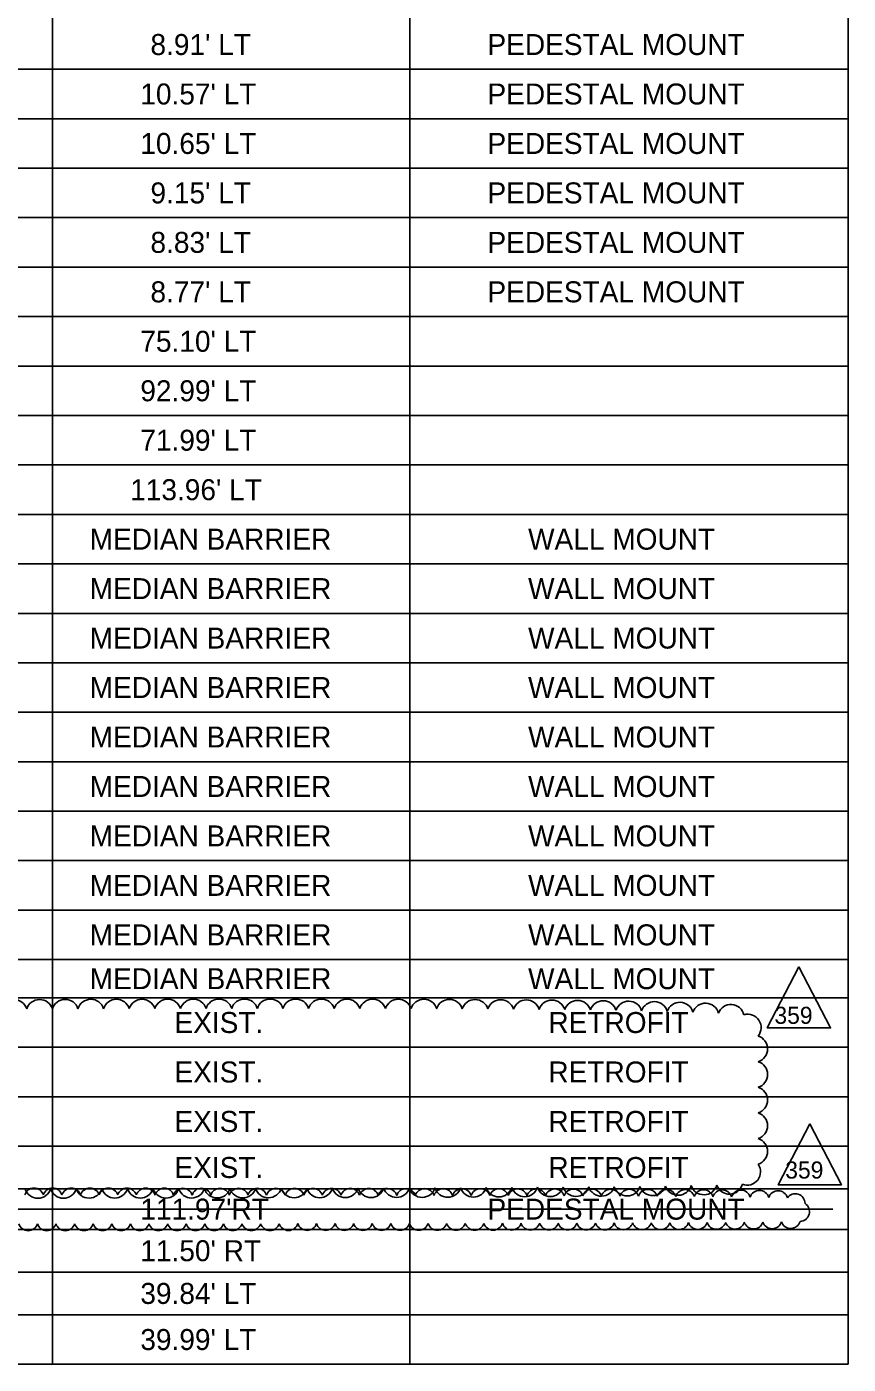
# Model space of a CAD drawing. Extents: x -818.1 to -802.4, y -2221.2 to -2187.7.
# Drawn here: x -812.426 to -809.686, y -2206.269 to -2201.807 of the extents above; entities that cross this region are included whole.
import ezdxf

# ---------------------------------------------------------------- set-up
doc = ezdxf.new("R2010")
doc.units = 0
for name, color, linetype in [('PlotBorder_dp', 7, 'Continuous'), ('SheetBorder_dp', 7, 'Continuous'), ('SheetLines_dp', 7, 'Continuous'), ('TextMinor', 7, 'Continuous'), ('TextTitle', 7, 'Continuous')]:
    doc.layers.add(name, color=color, linetype=linetype)

msp = doc.modelspace()

# ---------------------------------------------------------------- linework, layer by layer
at = {"layer": 'PlotBorder_dp'}
for p, q in [((-812.3407, -2199.8042), (-812.3407, -2206.2692)), ((-812.3407, -2199.8042), (-812.3407, -2206.2692)), ((-811.1482, -2199.8042), (-811.1482, -2206.2692)), ((-811.1482, -2199.8042), (-811.1482, -2206.2692))]:
    msp.add_line(p, q, dxfattribs=at)
at = {"layer": 'SheetLines_dp'}
for p, q in [((-809.6857, -2199.4742), (-809.6857, -2206.2692)), ((-817.2082, -2206.2692), (-811.1482, -2206.2692)), ((-811.1482, -2206.2692), (-809.6857, -2206.2692))]:
    msp.add_line(p, q, dxfattribs=at)
at = {"layer": 'TextMinor'}
for p, q in [((-817.2082, -2201.9492), (-809.6857, -2201.9492)), ((-817.2082, -2201.9492), (-809.6857, -2201.9492)), ((-817.2082, -2202.1142), (-809.6857, -2202.1142)), ((-817.2082, -2202.1142), (-809.6857, -2202.1142)), ((-817.2082, -2202.2792), (-809.6857, -2202.2792)), ((-817.2082, -2202.2792), (-809.6857, -2202.2792)), ((-817.2082, -2202.4442), (-809.6857, -2202.4442)), ((-817.2082, -2202.4442), (-809.6857, -2202.4442)), ((-817.2082, -2202.6092), (-809.6857, -2202.6092)), ((-817.2082, -2202.6092), (-809.6857, -2202.6092)), ((-817.2082, -2202.7742), (-809.6857, -2202.7742)), ((-817.2082, -2202.7742), (-809.6857, -2202.7742)), ((-817.2082, -2202.9392), (-809.6857, -2202.9392)), ((-817.2082, -2202.9392), (-809.6857, -2202.9392)), ((-817.2082, -2203.1042), (-809.6857, -2203.1042)), ((-817.2082, -2203.1042), (-809.6857, -2203.1042)), ((-817.2082, -2203.2692), (-809.6857, -2203.2692)), ((-817.2082, -2203.2692), (-809.6857, -2203.2692)), ((-817.2082, -2203.4342), (-809.6857, -2203.4342)), ((-817.2082, -2203.4342), (-809.6857, -2203.4342)), ((-817.2082, -2203.5992), (-809.6857, -2203.5992)), ((-817.2082, -2203.5992), (-809.6857, -2203.5992)), ((-817.2082, -2203.7642), (-809.6857, -2203.7642)), ((-817.2082, -2203.7642), (-809.6857, -2203.7642)), ((-817.2082, -2203.9292), (-809.6857, -2203.9292)), ((-817.2082, -2203.9292), (-809.6857, -2203.9292)), ((-817.2082, -2204.0942), (-809.6857, -2204.0942)), ((-817.2082, -2204.0942), (-809.6857, -2204.0942)), ((-817.2082, -2204.2592), (-809.6857, -2204.2592)), ((-817.2082, -2204.2592), (-809.6857, -2204.2592)), ((-817.2082, -2204.4242), (-809.6857, -2204.4242)), ((-817.2082, -2204.4242), (-809.6857, -2204.4242)), ((-817.2082, -2204.5892), (-809.6857, -2204.5892)), ((-817.2082, -2204.5892), (-809.6857, -2204.5892)), ((-817.2082, -2204.7542), (-809.6857, -2204.7542)), ((-817.2082, -2204.7542), (-809.6857, -2204.7542)), ((-817.2082, -2204.9192), (-809.6857, -2204.9192)), ((-816.2257, -2204.9192), (-809.6857, -2204.9192)), ((-817.2082, -2205.0467), (-809.6857, -2205.0467)), ((-817.2082, -2205.0467), (-809.6857, -2205.0467)), ((-817.2082, -2205.2117), (-809.6857, -2205.2117)), ((-814.2457, -2205.2117), (-809.6857, -2205.2117)), ((-817.2082, -2205.3767), (-809.6857, -2205.3767)), ((-812.9482, -2205.3767), (-809.6857, -2205.3767)), ((-817.2082, -2205.5417), (-809.6857, -2205.5417)), ((-814.2457, -2205.5417), (-809.6857, -2205.5417)), ((-817.2082, -2205.6842), (-809.6857, -2205.6842)), ((-812.9482, -2205.6842), (-809.6857, -2205.6842)), ((-817.2082, -2205.8192), (-809.6857, -2205.8192)), ((-816.7882, -2205.8192), (-811.1482, -2205.8192)), ((-817.2082, -2205.9617), (-809.6857, -2205.9617)), ((-817.2082, -2206.1042), (-809.6857, -2206.1042)), ((-813.6457, -2206.1042), (-811.1482, -2206.1042))]:
    msp.add_line(p, q, dxfattribs=at)
at = {"layer": 'TextTitle'}
msp.add_line((-817.0974, -2205.7517), (-809.7376, -2205.7517), dxfattribs=at)
for points in [[(-809.85, -2204.9439), (-809.9557, -2205.1473), (-809.7444, -2205.1473)], [(-809.8139, -2205.4676), (-809.9195, -2205.6711), (-809.7083, -2205.6711)]]:
    msp.add_lwpolyline(points, close=True, dxfattribs=at)
for centre, radius, start, end in [((-812.2982, -2205.0969), 0.0448, 17.6898, 162.6898), ((-812.2127, -2205.0966), 0.0448, 17.6723, 162.6723), ((-812.1272, -2205.0964), 0.0448, 17.6538, 162.6538), ((-812.0418, -2205.0962), 0.0448, 17.6341, 162.6341), ((-811.9563, -2205.096), 0.0448, 17.6131, 162.6131), ((-811.8708, -2205.0959), 0.0448, 17.5908, 162.5908), ((-811.7854, -2205.0957), 0.0448, 17.5668, 162.5668), ((-811.6999, -2205.0957), 0.0448, 17.5411, 162.5411), ((-811.6144, -2205.0956), 0.0448, 17.5134, 162.5134), ((-811.529, -2205.0956), 0.0448, 17.4834, 162.4834), ((-811.4435, -2205.0957), 0.0448, 17.4509, 162.4509), ((-811.358, -2205.0958), 0.0448, 17.4153, 162.4153), ((-811.2726, -2205.0959), 0.0448, 17.3762, 162.3762), ((-811.1871, -2205.0961), 0.0448, 17.333, 162.333), ((-811.1016, -2205.0964), 0.0448, 17.285, 162.285), ((-811.0162, -2205.0968), 0.0448, 17.231, 162.231), ((-812.4691, -2205.0975), 0.0448, 17.7221, 162.7221), ((-812.3837, -2205.0972), 0.0448, 17.7064, 162.7064), ((-810.9307, -2205.0972), 0.0448, 17.1699, 162.1699), ((-810.8452, -2205.0978), 0.0448, 17.0999, 162.0999), ((-810.7598, -2205.0984), 0.0448, 17.0185, 162.0185), ((-810.6743, -2205.0992), 0.0448, 16.9224, 161.9224), ((-810.5889, -2205.1002), 0.0448, 16.8064, 161.8064), ((-810.5035, -2205.1013), 0.0448, 16.6627, 161.6627), ((-810.418, -2205.1027), 0.0448, 16.4778, 161.4778), ((-810.3326, -2205.1044), 0.0448, 16.2276, 161.2276), ((-810.2473, -2205.1066), 0.0448, 15.861, 160.861), ((-810.162, -2205.1095), 0.0448, 15.2441, 160.2441), ((-810.077, -2205.1139), 0.0448, 13.804, 158.804), ((-810.021, -2205.1462), 0.0448, 321.1304, 106.1304), ((-809.9996, -2205.2171), 0.0448, 287.5, 72.5), ((-809.9996, -2205.3025), 0.0448, 287.5, 72.5), ((-809.9996, -2205.388), 0.0448, 287.5, 72.5), ((-809.9996, -2205.4735), 0.0448, 287.5, 72.5), ((-809.9996, -2205.559), 0.0448, 287.5, 72.5), ((-810.0231, -2205.627), 0.0448, 249.3736, 34.3736), ((-810.5091, -2205.6637), 0.0448, 198.0389, 343.0389), ((-810.4236, -2205.6629), 0.0448, 198.1252, 343.1252), ((-810.3382, -2205.6618), 0.0448, 198.2415, 343.2415), ((-810.2527, -2205.6606), 0.0448, 198.4108, 343.4108), ((-810.1673, -2205.659), 0.0448, 198.6925, 343.6925), ((-810.082, -2205.6568), 0.0448, 199.3286, 344.3286), ((-812.4021, -2205.714), 0.0325, 17.463, 162.463), ((-812.3894, -2205.6704), 0.0448, 197.5477, 342.5477), ((-812.3401, -2205.714), 0.0325, 17.4602, 162.4602), ((-812.3039, -2205.6704), 0.0448, 197.5556, 342.5556), ((-812.278, -2205.7141), 0.0325, 17.4573, 162.4573), ((-812.2184, -2205.6703), 0.0448, 197.5639, 342.5639), ((-812.216, -2205.7141), 0.0325, 17.4543, 162.4543), ((-812.1539, -2205.7142), 0.0325, 17.4512, 162.4512), ((-812.133, -2205.6702), 0.0448, 197.5726, 342.5726), ((-812.0919, -2205.7142), 0.0325, 17.448, 162.448), ((-812.0475, -2205.67), 0.0448, 197.5819, 342.5819), ((-812.0298, -2205.7143), 0.0325, 17.4446, 162.4446), ((-811.962, -2205.6699), 0.0448, 197.5918, 342.5918), ((-811.9677, -2205.7143), 0.0325, 17.4411, 162.4411), ((-811.9057, -2205.7144), 0.0325, 17.4374, 162.4374), ((-811.8765, -2205.6698), 0.0448, 197.6024, 342.6024), ((-811.8436, -2205.7145), 0.0325, 17.4335, 162.4335), ((-811.7911, -2205.6696), 0.0448, 197.6137, 342.6137), ((-811.7816, -2205.7146), 0.0325, 17.4294, 162.4294), ((-811.7195, -2205.7146), 0.0325, 17.4252, 162.4252), ((-811.7056, -2205.6694), 0.0448, 197.6259, 342.6259), ((-811.6575, -2205.7147), 0.0325, 17.4207, 162.4207), ((-811.6201, -2205.6692), 0.0448, 197.639, 342.639), ((-811.5954, -2205.7148), 0.0325, 17.416, 162.416), ((-811.5347, -2205.669), 0.0448, 197.6531, 342.6531), ((-811.5333, -2205.7149), 0.0325, 17.411, 162.411), ((-811.4713, -2205.715), 0.0325, 17.4057, 162.4057), ((-811.4492, -2205.6688), 0.0448, 197.6685, 342.6685), ((-811.4092, -2205.7151), 0.0325, 17.4002, 162.4002), ((-811.3637, -2205.6685), 0.0448, 197.6853, 342.6853), ((-811.3472, -2205.7152), 0.0325, 17.3942, 162.3942), ((-811.2782, -2205.6682), 0.0448, 197.7038, 342.7038), ((-811.2851, -2205.7153), 0.0325, 17.3879, 162.3879), ((-811.223, -2205.7155), 0.0325, 17.3812, 162.3812), ((-811.1928, -2205.6679), 0.0448, 197.7241, 342.7241), ((-811.161, -2205.7156), 0.0325, 17.374, 162.374), ((-811.1073, -2205.6676), 0.0448, 197.7468, 342.7468), ((-811.0989, -2205.7157), 0.0325, 17.3662, 162.3662), ((-811.0369, -2205.7159), 0.0325, 17.3579, 162.3579), ((-811.0218, -2205.6672), 0.0448, 197.7722, 342.7722), ((-810.9748, -2205.716), 0.0325, 17.3488, 162.3488), ((-810.9364, -2205.6667), 0.0448, 197.801, 342.801), ((-810.9128, -2205.7162), 0.0325, 17.339, 162.339), ((-810.8509, -2205.6663), 0.0448, 197.8339, 342.8339), ((-810.8507, -2205.7164), 0.0325, 17.3282, 162.3282), ((-810.7887, -2205.7166), 0.0325, 17.3164, 162.3164), ((-810.7654, -2205.6657), 0.0448, 197.8722, 342.8722), ((-810.7266, -2205.7168), 0.0325, 17.3033, 162.3033), ((-810.68, -2205.6651), 0.0448, 197.9173, 342.9173), ((-810.6645, -2205.717), 0.0325, 17.2888, 162.2888), ((-810.5945, -2205.6645), 0.0448, 197.9717, 342.9717), ((-810.6025, -2205.7172), 0.0325, 17.2724, 162.2724), ((-810.5404, -2205.7175), 0.0325, 17.2538, 162.2538), ((-810.4784, -2205.7178), 0.0325, 17.2324, 162.2324), ((-810.4163, -2205.7181), 0.0325, 17.2076, 162.2076), ((-810.3543, -2205.7184), 0.0325, 17.1781, 162.1781), ((-810.2922, -2205.7188), 0.0325, 17.1424, 162.1424), ((-810.2302, -2205.7192), 0.0325, 17.098, 162.098), ((-810.1681, -2205.7197), 0.0325, 17.0404, 162.0404), ((-810.1061, -2205.7202), 0.0325, 16.9617, 161.9617), ((-810.044, -2205.7208), 0.0325, 16.8443, 161.8443), ((-809.982, -2205.7217), 0.0325, 16.6401, 161.6401), ((-809.9201, -2205.7229), 0.0325, 16.1079, 161.1079), ((-809.8623, -2205.7327), 0.0325, 359.6037, 144.6037), ((-809.8475, -2205.7602), 0.0325, 271.8825, 56.8825), ((-812.4218, -2205.7911), 0.0325, 197.5287, 342.5287), ((-812.3598, -2205.7911), 0.0325, 197.531, 342.531), ((-812.2977, -2205.7911), 0.0325, 197.5333, 342.5333), ((-812.2356, -2205.791), 0.0325, 197.5357, 342.5357), ((-812.1736, -2205.791), 0.0325, 197.5382, 342.5382), ((-812.1115, -2205.791), 0.0325, 197.5408, 342.5408), ((-812.0495, -2205.7909), 0.0325, 197.5435, 342.5435), ((-811.9874, -2205.7909), 0.0325, 197.5464, 342.5464), ((-811.9254, -2205.7908), 0.0325, 197.5493, 342.5493), ((-811.8633, -2205.7908), 0.0325, 197.5524, 342.5524), ((-811.8012, -2205.7907), 0.0325, 197.5557, 342.5557), ((-811.7392, -2205.7906), 0.0325, 197.5591, 342.5591), ((-811.6771, -2205.7906), 0.0325, 197.5627, 342.5627), ((-811.6151, -2205.7905), 0.0325, 197.5664, 342.5664), ((-811.553, -2205.7904), 0.0325, 197.5704, 342.5704), ((-811.491, -2205.7903), 0.0325, 197.5745, 342.5745), ((-811.4289, -2205.7903), 0.0325, 197.579, 342.579), ((-811.3668, -2205.7902), 0.0325, 197.5836, 342.5836), ((-811.3048, -2205.7901), 0.0325, 197.5886, 342.5886), ((-811.2427, -2205.79), 0.0325, 197.5939, 342.5939), ((-811.1807, -2205.7899), 0.0325, 197.5996, 342.5996), ((-811.1186, -2205.7898), 0.0325, 197.6056, 342.6056), ((-811.0565, -2205.7897), 0.0325, 197.6121, 342.6121), ((-810.9945, -2205.7895), 0.0325, 197.6192, 342.6192), ((-810.9324, -2205.7894), 0.0325, 197.6268, 342.6268), ((-810.8704, -2205.7893), 0.0325, 197.6351, 342.6351), ((-810.8083, -2205.7891), 0.0325, 197.6441, 342.6441), ((-810.7463, -2205.7889), 0.0325, 197.6541, 342.6541), ((-810.6842, -2205.7888), 0.0325, 197.6651, 342.6651), ((-810.6222, -2205.7886), 0.0325, 197.6774, 342.6774), ((-810.5601, -2205.7884), 0.0325, 197.6912, 342.6912), ((-810.498, -2205.7882), 0.0325, 197.7069, 342.7069), ((-810.436, -2205.7879), 0.0325, 197.725, 342.725), ((-810.3739, -2205.7877), 0.0325, 197.7461, 342.7461), ((-810.3119, -2205.7874), 0.0325, 197.7711, 342.7711), ((-810.2498, -2205.7871), 0.0325, 197.8015, 342.8015), ((-810.1878, -2205.7867), 0.0325, 197.8394, 342.8394), ((-810.1257, -2205.7863), 0.0325, 197.8888, 342.8888), ((-810.0637, -2205.7859), 0.0325, 197.9568, 342.9568), ((-810.0016, -2205.7853), 0.0325, 198.0592, 343.0592), ((-809.9396, -2205.7846), 0.0325, 198.2413, 343.2413), ((-809.8777, -2205.7836), 0.0325, 198.7573, 343.7573)]:
    msp.add_arc(centre, radius, start, end, dxfattribs=at)

# ---------------------------------------------------------------- texts
at = {"layer": 'SheetBorder_dp'}
for s, p in [("8.91' LT", (-812.0137, -2201.9017)), ('PEDESTAL MOUNT', (-810.8894, -2201.9017)), ("10.57' LT", (-812.0475, -2202.0667)), ('PEDESTAL MOUNT', (-810.8894, -2202.0667)), ("10.65' LT", (-812.0475, -2202.2317)), ('PEDESTAL MOUNT', (-810.8894, -2202.2317)), ("9.15' LT", (-812.0137, -2202.3967)), ('PEDESTAL MOUNT', (-810.8894, -2202.3967)), ("8.83' LT", (-812.0137, -2202.5617)), ('PEDESTAL MOUNT', (-810.8894, -2202.5617)), ("8.77' LT", (-812.0137, -2202.7267)), ('PEDESTAL MOUNT', (-810.8894, -2202.7267)), ("75.10' LT", (-812.0475, -2202.8917)), ("92.99' LT", (-812.0475, -2203.0567)), ("71.99' LT", (-812.0475, -2203.2217)), ("113.96' LT", (-812.0814, -2203.3867)), ('MEDIAN BARRIER', (-812.2165, -2203.5517)), ('WALL MOUNT', (-810.7539, -2203.5517)), ('MEDIAN BARRIER', (-812.2165, -2203.7167)), ('WALL MOUNT', (-810.7539, -2203.7167)), ('MEDIAN BARRIER', (-812.2165, -2203.8817)), ('WALL MOUNT', (-810.7539, -2203.8817)), ('MEDIAN BARRIER', (-812.2165, -2204.0467)), ('WALL MOUNT', (-810.7539, -2204.0467)), ('MEDIAN BARRIER', (-812.2165, -2204.2117)), ('WALL MOUNT', (-810.7539, -2204.2117)), ('MEDIAN BARRIER', (-812.2165, -2204.3767)), ('WALL MOUNT', (-810.7539, -2204.3767)), ('MEDIAN BARRIER', (-812.2165, -2204.5417)), ('WALL MOUNT', (-810.7539, -2204.5417)), ('MEDIAN BARRIER', (-812.2165, -2204.7067)), ('WALL MOUNT', (-810.7539, -2204.7067)), ('MEDIAN BARRIER', (-812.2165, -2204.8717)), ('WALL MOUNT', (-810.7539, -2204.8717)), ('MEDIAN BARRIER', (-812.2165, -2205.0179)), ('WALL MOUNT', (-810.7539, -2205.0179)), ('EXIST.', (-811.9337, -2205.1642)), ('RETROFIT', (-810.6862, -2205.1642)), ('EXIST.', (-811.9337, -2205.3292)), ('RETROFIT', (-810.6862, -2205.3292)), ('EXIST.', (-811.9337, -2205.4942)), ('RETROFIT', (-810.6862, -2205.4942)), ('EXIST.', (-811.9337, -2205.6479)), ('RETROFIT', (-810.6862, -2205.6479)), ("111.97'RT", (-812.0475, -2205.7867)), ('PEDESTAL MOUNT', (-810.8894, -2205.7867)), ("11.50' RT", (-812.0475, -2205.9254)), ("39.84' LT", (-812.0475, -2206.0679)), ("39.99' LT", (-812.0475, -2206.2217))]:
    msp.add_text(s, height=0.07, dxfattribs=at).set_placement(p)
at = {"layer": 'TextTitle'}
for p in [(-809.9319, -2205.1336), (-809.8958, -2205.6497)]:
    msp.add_text('359', height=0.057, dxfattribs=at).set_placement(p)

doc.saveas('drawing.dxf')
